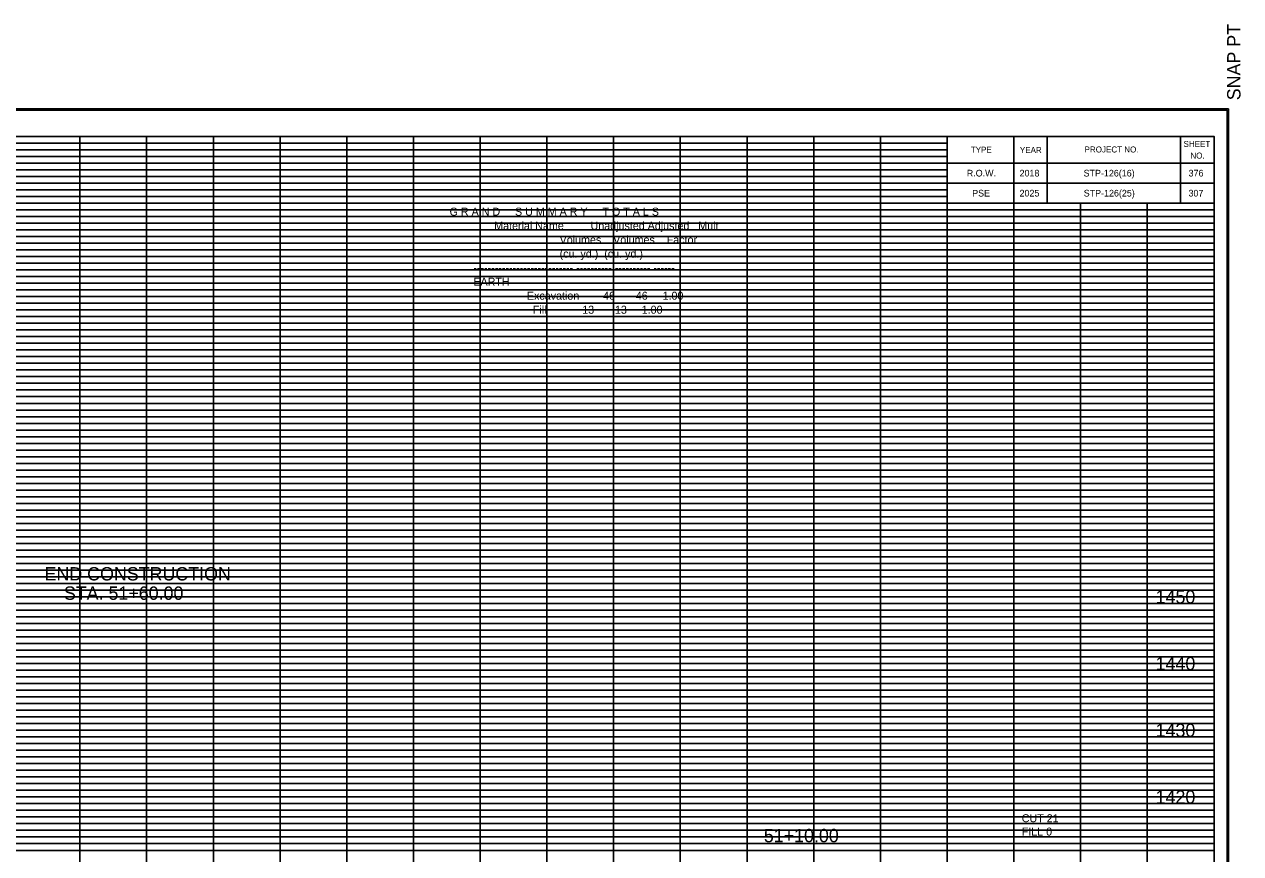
# Model space of a CAD drawing. Extents: x 980 to 1324, y 978 to 1227.
# Drawn here: x 1141.7 to 1324, y 1102.5 to 1226.8 of the extents above; entities that cross this region are included whole.
import ezdxf

# ---------------------------------------------------------------- set-up
doc = ezdxf.new("R2010")
doc.units = 0
for name, color, linetype in [('DESIGN - SCRATCH - User 1', 7, 'Continuous'), ('DESIGN - SHEET - Corner Text', 7, 'Continuous'), ('DESIGN - SHEET - Light Grid', 7, 'Continuous'), ('DESIGN - SHEET - Linework', 7, 'Continuous'), ('DESIGN - SHEET - Plot Shape', 7, 'Continuous'), ('DESIGN - TYPICAL - Finished Grade and Subgrade', 7, 'Continuous'), ('DESIGN - TYPICAL - Text', 7, 'Continuous')]:
    doc.layers.add(name, color=color, linetype=linetype)

# ---------------------------------------------------------------- blocks, each defined once
blk = doc.blocks.new('XSTSHT')
at = {"layer": 'DESIGN - SCRATCH - User 1'}
for p, q in [((28.5, 20.45), (28.5, 20.45)), ((29.24, 20.45), (29.24, 20.45)), ((30.49, 20.45), (30.49, 20.45)), ((31.74, 20.45), (31.74, 20.45)), ((28.5, 20.15), (28.5, 20.15)), ((29.24, 20.15), (29.24, 20.15)), ((30.49, 20.15), (30.49, 20.15)), ((31.74, 20.15), (31.74, 20.15))]:
    blk.add_line(p, q, dxfattribs=at)
at = {"layer": 'DESIGN - SHEET - Light Grid'}
for p, q in [((8, 20.9), (16, 20.9)), ((8, 20.8), (16, 20.8)), ((16, 20.9), (24, 20.9)), ((16, 20.8), (24, 20.8)), ((24, 20.9), (28, 20.9)), ((24, 20.8), (28, 20.8)), ((8, 20.7), (16, 20.7)), ((16, 20.7), (24, 20.7)), ((24, 20.7), (28, 20.7)), ((8, 20.6), (16, 20.6)), ((8, 20.5), (16, 20.5)), ((16, 20.6), (24, 20.6)), ((16, 20.5), (24, 20.5)), ((24, 20.6), (28, 20.6)), ((24, 20.5), (28, 20.5)), ((8, 20.4), (16, 20.4)), ((8, 20.3), (16, 20.3)), ((16, 20.4), (24, 20.4)), ((16, 20.3), (24, 20.3)), ((24, 20.4), (28, 20.4)), ((24, 20.3), (28, 20.3)), ((8, 20.2), (16, 20.2)), ((8, 20.1), (16, 20.1)), ((16, 20.2), (24, 20.2)), ((16, 20.1), (24, 20.1)), ((24, 20.2), (28, 20.2)), ((24, 20.1), (28, 20.1)), ((8, 19.9), (16, 19.9)), ((16, 19.9), (24, 19.9)), ((24, 19.9), (32, 19.9)), ((8, 19.8), (16, 19.8)), ((8, 19.7), (16, 19.7)), ((16, 19.8), (24, 19.8)), ((16, 19.7), (24, 19.7)), ((24, 19.8), (32, 19.8)), ((24, 19.7), (32, 19.7)), ((8, 19.6), (16, 19.6)), ((16, 19.6), (24, 19.6)), ((24, 19.6), (32, 19.6)), ((8, 19.5), (16, 19.5)), ((8, 19.4), (16, 19.4)), ((16, 19.5), (24, 19.5)), ((16, 19.4), (24, 19.4)), ((24, 19.5), (32, 19.5)), ((24, 19.4), (32, 19.4)), ((8, 19.3), (16, 19.3)), ((8, 19.2), (16, 19.2)), ((16, 19.3), (24, 19.3)), ((16, 19.2), (24, 19.2)), ((24, 19.3), (32, 19.3)), ((24, 19.2), (32, 19.2)), ((8, 19.1), (16, 19.1)), ((16, 19.1), (24, 19.1)), ((24, 19.1), (32, 19.1)), ((8, 18.9), (16, 18.9)), ((8, 18.8), (16, 18.8)), ((16, 18.9), (24, 18.9)), ((16, 18.8), (24, 18.8)), ((24, 18.9), (32, 18.9)), ((24, 18.8), (32, 18.8)), ((8, 18.7), (16, 18.7)), ((8, 18.6), (16, 18.6)), ((16, 18.7), (24, 18.7)), ((16, 18.6), (24, 18.6)), ((24, 18.7), (32, 18.7)), ((24, 18.6), (32, 18.6)), ((8, 18.5), (16, 18.5)), ((16, 18.5), (24, 18.5)), ((24, 18.5), (32, 18.5)), ((8, 18.4), (16, 18.4)), ((8, 18.3), (16, 18.3)), ((16, 18.4), (24, 18.4)), ((16, 18.3), (24, 18.3)), ((24, 18.4), (32, 18.4)), ((24, 18.3), (32, 18.3)), ((8, 18.2), (16, 18.2)), ((8, 18.1), (16, 18.1)), ((16, 18.2), (24, 18.2)), ((16, 18.1), (24, 18.1)), ((24, 18.2), (32, 18.2)), ((24, 18.1), (32, 18.1)), ((8, 17.9), (16, 17.9)), ((16, 17.9), (24, 17.9)), ((24, 17.9), (32, 17.9)), ((8, 17.8), (16, 17.8)), ((8, 17.7), (16, 17.7)), ((16, 17.8), (24, 17.8)), ((16, 17.7), (24, 17.7)), ((24, 17.8), (32, 17.8)), ((24, 17.7), (32, 17.7)), ((8, 17.6), (16, 17.6)), ((16, 17.6), (24, 17.6)), ((24, 17.6), (32, 17.6)), ((8, 17.5), (16, 17.5)), ((8, 17.4), (16, 17.4)), ((16, 17.5), (24, 17.5)), ((16, 17.4), (24, 17.4)), ((24, 17.5), (32, 17.5)), ((24, 17.4), (32, 17.4)), ((8, 17.3), (16, 17.3)), ((8, 17.2), (16, 17.2)), ((16, 17.3), (24, 17.3)), ((16, 17.2), (24, 17.2)), ((24, 17.3), (32, 17.3)), ((24, 17.2), (32, 17.2)), ((8, 17.1), (16, 17.1)), ((16, 17.1), (24, 17.1)), ((24, 17.1), (32, 17.1)), ((8, 16.9), (16, 16.9)), ((8, 16.8), (16, 16.8)), ((16, 16.9), (24, 16.9)), ((16, 16.8), (24, 16.8)), ((24, 16.9), (32, 16.9)), ((24, 16.8), (32, 16.8)), ((8, 16.7), (16, 16.7)), ((8, 16.6), (16, 16.6)), ((16, 16.7), (24, 16.7)), ((16, 16.6), (24, 16.6)), ((24, 16.7), (32, 16.7)), ((24, 16.6), (32, 16.6)), ((8, 16.5), (16, 16.5)), ((16, 16.5), (24, 16.5)), ((24, 16.5), (32, 16.5)), ((8, 16.4), (16, 16.4)), ((8, 16.3), (16, 16.3)), ((16, 16.4), (24, 16.4)), ((16, 16.3), (24, 16.3)), ((24, 16.4), (32, 16.4)), ((24, 16.3), (32, 16.3)), ((8, 16.2), (16, 16.2)), ((8, 16.1), (16, 16.1)), ((16, 16.2), (24, 16.2)), ((16, 16.1), (24, 16.1)), ((24, 16.2), (32, 16.2)), ((24, 16.1), (32, 16.1)), ((8, 15.9), (16, 15.9)), ((16, 15.9), (24, 15.9)), ((24, 15.9), (32, 15.9)), ((8, 15.8), (16, 15.8)), ((8, 15.7), (16, 15.7)), ((16, 15.8), (24, 15.8)), ((16, 15.7), (24, 15.7)), ((24, 15.8), (32, 15.8)), ((24, 15.7), (32, 15.7)), ((8, 15.6), (16, 15.6)), ((8, 15.5), (16, 15.5)), ((16, 15.6), (24, 15.6)), ((16, 15.5), (24, 15.5)), ((24, 15.6), (32, 15.6)), ((24, 15.5), (32, 15.5)), ((8, 15.4), (16, 15.4)), ((16, 15.4), (24, 15.4)), ((24, 15.4), (32, 15.4)), ((8, 15.3), (16, 15.3)), ((8, 15.2), (16, 15.2)), ((16, 15.3), (24, 15.3)), ((16, 15.2), (24, 15.2)), ((24, 15.3), (32, 15.3)), ((24, 15.2), (32, 15.2)), ((8, 15.1), (16, 15.1)), ((16, 15.1), (24, 15.1)), ((24, 15.1), (32, 15.1)), ((8, 14.9), (16, 14.9)), ((8, 14.8), (16, 14.8)), ((16, 14.9), (24, 14.9)), ((16, 14.8), (24, 14.8)), ((24, 14.9), (32, 14.9)), ((24, 14.8), (32, 14.8)), ((8, 14.7), (16, 14.7)), ((8, 14.6), (16, 14.6)), ((16, 14.7), (24, 14.7)), ((16, 14.6), (24, 14.6)), ((24, 14.7), (32, 14.7)), ((24, 14.6), (32, 14.6)), ((8, 14.5), (16, 14.5)), ((16, 14.5), (24, 14.5)), ((24, 14.5), (32, 14.5)), ((8, 14.4), (16, 14.4)), ((8, 14.3), (16, 14.3)), ((16, 14.4), (24, 14.4)), ((16, 14.3), (24, 14.3)), ((24, 14.4), (32, 14.4)), ((24, 14.3), (32, 14.3)), ((8, 14.2), (16, 14.2)), ((8, 14.1), (16, 14.1)), ((16, 14.2), (24, 14.2)), ((16, 14.1), (24, 14.1)), ((24, 14.2), (32, 14.2)), ((24, 14.1), (32, 14.1)), ((8, 13.9), (16, 13.9)), ((16, 13.9), (24, 13.9)), ((24, 13.9), (32, 13.9)), ((8, 13.8), (16, 13.8)), ((8, 13.7), (16, 13.7)), ((16, 13.8), (24, 13.8)), ((16, 13.7), (24, 13.7)), ((24, 13.8), (32, 13.8)), ((24, 13.7), (32, 13.7)), ((8, 13.6), (16, 13.6)), ((8, 13.5), (16, 13.5)), ((16, 13.6), (24, 13.6)), ((16, 13.5), (24, 13.5)), ((24, 13.6), (32, 13.6)), ((24, 13.5), (32, 13.5)), ((8, 13.4), (16, 13.4)), ((16, 13.4), (24, 13.4)), ((24, 13.4), (32, 13.4)), ((8, 13.3), (16, 13.3)), ((8, 13.2), (16, 13.2)), ((16, 13.3), (24, 13.3)), ((16, 13.2), (24, 13.2)), ((24, 13.3), (32, 13.3)), ((24, 13.2), (32, 13.2)), ((8, 13.1), (16, 13.1)), ((16, 13.1), (24, 13.1)), ((24, 13.1), (32, 13.1)), ((8, 12.9), (16, 12.9)), ((8, 12.8), (16, 12.8)), ((16, 12.9), (24, 12.9)), ((16, 12.8), (24, 12.8)), ((24, 12.9), (32, 12.9)), ((24, 12.8), (32, 12.8)), ((8, 12.7), (16, 12.7)), ((8, 12.6), (16, 12.6)), ((16, 12.7), (24, 12.7)), ((16, 12.6), (24, 12.6)), ((24, 12.7), (32, 12.7)), ((24, 12.6), (32, 12.6)), ((8, 12.5), (16, 12.5)), ((8, 12.4), (16, 12.4)), ((16, 12.5), (24, 12.5)), ((16, 12.4), (24, 12.4)), ((24, 12.5), (32, 12.5)), ((24, 12.4), (32, 12.4)), ((8, 12.3), (16, 12.3)), ((16, 12.3), (24, 12.3)), ((24, 12.3), (32, 12.3)), ((8, 12.2), (16, 12.2)), ((8, 12.1), (16, 12.1)), ((16, 12.2), (24, 12.2)), ((16, 12.1), (24, 12.1)), ((24, 12.2), (32, 12.2)), ((24, 12.1), (32, 12.1)), ((8, 11.9), (16, 11.9)), ((16, 11.9), (24, 11.9)), ((24, 11.9), (32, 11.9)), ((8, 11.8), (16, 11.8)), ((8, 11.7), (16, 11.7)), ((16, 11.8), (24, 11.8)), ((16, 11.7), (24, 11.7)), ((24, 11.8), (32, 11.8)), ((24, 11.7), (32, 11.7)), ((8, 11.6), (16, 11.6)), ((8, 11.5), (16, 11.5)), ((16, 11.6), (24, 11.6)), ((16, 11.5), (24, 11.5)), ((24, 11.6), (32, 11.6)), ((24, 11.5), (32, 11.5)), ((8, 11.4), (16, 11.4)), ((16, 11.4), (24, 11.4)), ((24, 11.4), (32, 11.4)), ((8, 11.3), (16, 11.3)), ((8, 11.2), (16, 11.2)), ((16, 11.3), (24, 11.3)), ((16, 11.2), (24, 11.2)), ((24, 11.3), (32, 11.3)), ((24, 11.2), (32, 11.2)), ((8, 11.1), (16, 11.1)), ((16, 11.1), (24, 11.1)), ((24, 11.1), (32, 11.1)), ((8, 10.9), (16, 10.9)), ((8, 10.8), (16, 10.8)), ((16, 10.9), (24, 10.9)), ((16, 10.8), (24, 10.8)), ((24, 10.9), (32, 10.9)), ((24, 10.8), (32, 10.8)), ((8, 10.7), (16, 10.7)), ((8, 10.6), (16, 10.6)), ((16, 10.7), (24, 10.7)), ((16, 10.6), (24, 10.6)), ((24, 10.7), (32, 10.7)), ((24, 10.6), (32, 10.6)), ((8, 10.5), (16, 10.5)), ((8, 10.4), (16, 10.4)), ((16, 10.5), (24, 10.5)), ((16, 10.4), (24, 10.4)), ((24, 10.5), (32, 10.5)), ((24, 10.4), (32, 10.4)), ((8, 10.3), (16, 10.3)), ((16, 10.3), (24, 10.3)), ((24, 10.3), (32, 10.3))]:
    blk.add_line(p, q, dxfattribs=at)
at = {"layer": 'DESIGN - SHEET - Linework'}
for p, q in [((-1.823, 21.414), (32.217, 21.414)), ((32.217, 21.414), (32.217, -0.414)), ((15, 0), (15, 21)), ((16, 0), (16, 21)), ((17, 0), (17, 21)), ((18, 0), (18, 21)), ((19, 0), (19, 21)), ((20, 0), (20, 21)), ((21, 0), (21, 21)), ((22, 0), (22, 21)), ((23, 0), (23, 21)), ((24, 0), (24, 21)), ((25, 0), (25, 21)), ((26, 0), (26, 21)), ((27, 0), (27, 21)), ((0, 20), (28, 20)), ((28, 0), (28, 20)), ((29, 0), (29, 20)), ((30, 0), (30, 20)), ((31, 0), (31, 20)), ((0, 19), (32, 19)), ((0, 18), (32, 18)), ((0, 17), (32, 17)), ((0, 16), (32, 16)), ((0, 15), (32, 15)), ((0, 14), (32, 14)), ((0, 13), (32, 13)), ((0, 12), (32, 12)), ((0, 11), (32, 11))]:
    blk.add_line(p, q, dxfattribs=at)
for points in [[(0, 21), (0, 0), (32, 0), (32, 21), (0, 21)], [(28, 21), (28, 20), (32, 20), (32, 21), (31.5, 21), (31.5, 20), (29.5, 20), (29.5, 21), (29, 21), (29, 20), (32, 20), (28, 20), (28, 20.3), (32, 20.3), (32, 20.6), (28, 20.6)]]:
    blk.add_lwpolyline(points, dxfattribs=at)
at = {"layer": 'DESIGN - SHEET - Plot Shape'}
for points in [[(-1.803, 21.394), (32.197, 21.394), (32.197, -0.394), (-1.803, -0.394)], [(-0.85, 21), (32, 21), (32, -0.25), (-0.85, -0.25)]]:
    blk.add_lwpolyline(points, close=True, dxfattribs=at)
at = {"layer": 'DESIGN - SHEET - Corner Text'}
blk.add_text('  SNAP PT', height=0.2, rotation=90, dxfattribs=at).set_placement((32.397, 21.394))
for s, p in [('TYPE', (28.354, 20.756)), ('YEAR', (29.09, 20.752)), ('PROJECT NO.', (30.06, 20.76)), ('SHEET', (31.543, 20.843)), ('NO.', (31.646, 20.669))]:
    blk.add_text(s, height=0.09, dxfattribs=at).set_placement(p)

msp = doc.modelspace()

# ---------------------------------------------------------------- linework, layer by layer
at = {"layer": 'DESIGN - SHEET - Plot Shape'}
msp.add_lwpolyline([(991.5, 997.5), (1320, 997.5), (1320, 1210), (991.5, 1210)], close=True, dxfattribs=at)

# ---------------------------------------------------------------- block references
at = {"layer": 'DESIGN - TYPICAL - Finished Grade and Subgrade', "xscale": 10, "yscale": 10}
msp.add_blockref('XSTSHT', (1000, 1000), dxfattribs=at)

# ---------------------------------------------------------------- texts
at = {"layer": 'DESIGN - SHEET - Corner Text'}
for s, height, p in [('R.O.W.', 1, (1282.94, 1204)), ('2018', 1, (1290.85, 1204)), ('STP-126(16)', 1, (1300.45, 1204)), ('376', 1, (1316.19, 1204)), ('PSE', 1, (1283.75, 1201)), ('2025', 1, (1290.85, 1201)), ('STP-126(25)', 1, (1300.47, 1201)), ('307', 1, (1316.18, 1201)), ('1450', 2, (1311.25, 1140)), ('1440', 2, (1311.25, 1130)), ('1430', 2, (1311.25, 1120)), ('1420', 2, (1311.25, 1110)), ('51+10.00', 2, (1252.52, 1104.21))]:
    msp.add_text(s, height=height, dxfattribs=at).set_placement(p)
at = {"layer": 'DESIGN - TYPICAL - Text'}
for s, height, p in [('G R A N D     S U M M A R Y     T O T A L S', 1.2, (1205.41, 1198.13)), ('               Material Name         Unadjusted Adjusted   Mult', 1.2, (1205.41, 1196.03)), ('                                     Volumes    Volumes    Factor', 1.2, (1205.41, 1193.93)), ('                                     (cu. yd.)  (cu. yd.)', 1.2, (1205.41, 1191.83)), ('        ---------------------------- ---------- ---------- ------', 1.2, (1205.41, 1189.73)), ('        EARTH', 1.2, (1205.41, 1187.63)), ('                          Excavation        46       46     1.00', 1.2, (1205.41, 1185.53)), ('                            Fill            13       13     1.00', 1.2, (1205.41, 1183.43)), ('END CONSTRUCTION', 2, (1144.69, 1143.45)), ('STA. 51+60.00', 2, (1147.59, 1140.55)), ('CUT 21', 1.2, (1291.18, 1107.21)), ('FILL 0', 1.2, (1291.18, 1105.21))]:
    msp.add_text(s, height=height, dxfattribs=at).set_placement(p)

doc.saveas('drawing.dxf')
